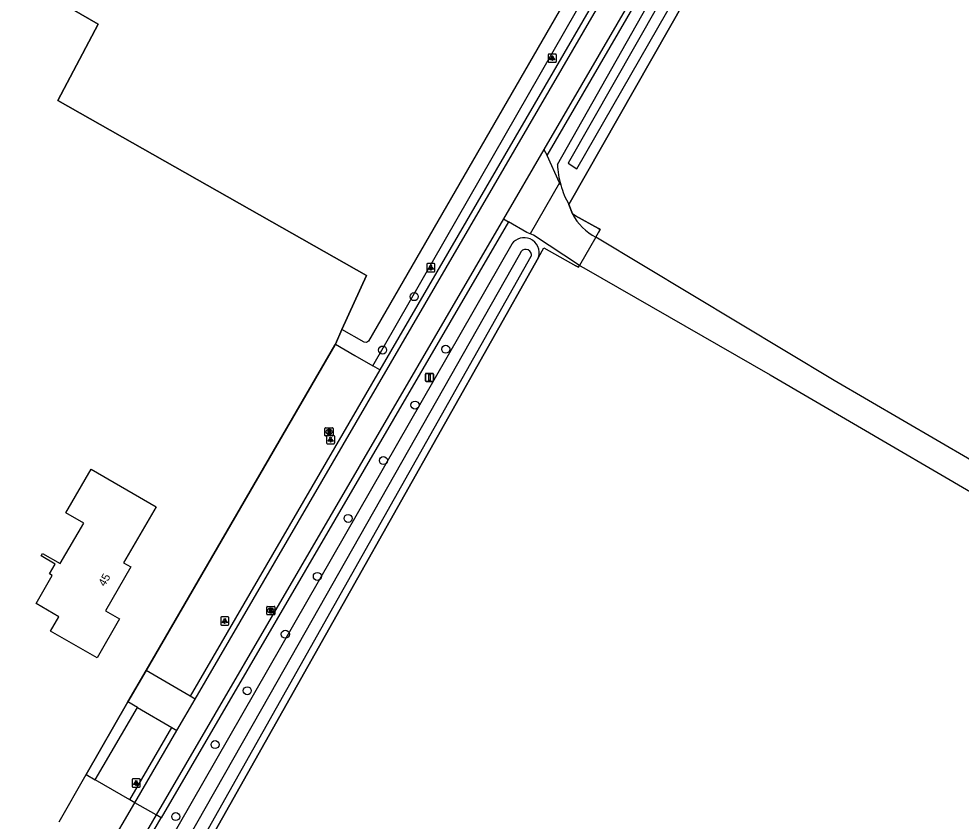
# Model space of a CAD drawing. Extents: x 156502 to 159074, y 384229 to 386094.
# Drawn here: x 157332.2 to 157446.9, y 385788.7 to 385886.4 of the extents above; entities that cross this region are included whole.
import ezdxf

# ---------------------------------------------------------------- set-up
doc = ezdxf.new("R2010")
doc.units = 0
for name, color, linetype in [('IMGEO_Boom', 7, 'Continuous'), ('IMGEO_Gemengd_bos', 7, 'Continuous'), ('IMGEO_Grasland_overig', 7, 'Continuous'), ('IMGEO_Greppel_droge_sloot', 7, 'Continuous'), ('IMGEO_Groenvoorziening', 7, 'Continuous'), ('IMGEO_Hek', 7, 'Continuous'), ('IMGEO_Lichtpunt', 7, 'Continuous'), ('IMGEO_Pand', 7, 'Continuous'), ('IMGEO_Pand_nummerreeks', 7, 'Continuous'), ('IMGEO_Rijbaan_lokaal_gesloten', 7, 'Continuous'), ('IMGEO_Rijbaan_lokaal_halfverhard', 7, 'Continuous'), ('IMGEO_Rijbaan_lokaal_onverhard', 7, 'Continuous'), ('IMGEO_Rijbaan_lokaal_open', 7, 'Continuous'), ('IMGEO_Rioolput', 7, 'Continuous'), ('IMGEO_Verkeersbordpaal', 7, 'Continuous')]:
    doc.layers.add(name, color=color, linetype=linetype)

msp = doc.modelspace()

# ---------------------------------------------------------------- linework, layer by layer
at = {"layer": 'IMGEO_Boom'}
for centre in [(157380.34, 385852.55), (157376.49, 385846.05), (157384.18, 385846.15), (157380.44, 385839.35), (157376.59, 385832.59), (157372.3, 385825.54), (157368.55, 385818.48), (157364.65, 385811.44), (157360.02, 385804.56), (157356.1, 385798), (157351.31, 385789.23)]:
    msp.add_circle(centre, 0.489, dxfattribs=at)
at = {"layer": 'IMGEO_Gemengd_bos'}
for points in [[(157371.55, 385848.55), (157374.53, 385855.11), (157336.95, 385876.45), (157341.88, 385885.73), (157297.29, 385911.48), (157291.8, 385905.79), (157257.61, 385922.62), (157240.01, 385933.44), (157265.45, 385970.38), (157218.89, 386000), (157178.39, 386025.76)], [(157395.47, 385857.33), (157396.13, 385858.5), (157400.02, 385856.3), (157400.33, 385856.13), (157400.45, 385856.36)], [(157395.47, 385857.33), (157372.59, 385816.74), (157334.96, 385750), (157287.88, 385668.68), (157271.39, 385640.19), (157191.03, 385500), (157152.55, 385432.88), (157150.67, 385429.59), (157146.17, 385421.74)]]:
    msp.add_lwpolyline(points, dxfattribs=at)
at = {"layer": 'IMGEO_Grasland_overig'}
for points in [[(157397.77, 385868.65), (157428.58, 385923.13)], [(157399.18, 385863.76), (157431.49, 385920.54)], [(157402.46, 385859.79), (157402.78, 385860.35), (157402.98, 385860.72), (157402.78, 385860.83), (157399.98, 385862.41), (157399.61, 385862.62)]]:
    msp.add_lwpolyline(points, dxfattribs=at)
msp.add_arc((157409.36, 385869.3), 11.61, 183.2027, 195.7368, dxfattribs=at)
at = {"layer": 'IMGEO_Greppel_droge_sloot'}
for points in [[(157375.29, 385844.13), (157410.37, 385905.3), (157420.59, 385922.78), (157421.74, 385925.12)], [(157419.09, 385923.89), (157374.77, 385847.13), (157374.53, 385846.95), (157374.24, 385846.99), (157371.55, 385848.55)], [(157617.36, 385817.91), (157432.79, 385923.31), (157430.69, 385923.14), (157429.39, 385922.01), (157399.07, 385868.79), (157400.14, 385868.11), (157430.83, 385921.58), (157431.57, 385921.75), (157432.56, 385921.64), (157433.69, 385921.16), (157694.94, 385770.98), (157787.76, 385718.79), (157788.5, 385720.1), (157617.36, 385817.91)], [(157393.36, 385858.05), (157393.11, 385857.61), (157362.75, 385804.11), (157325.82, 385739.17), (157293.92, 385684.22), (157277.51, 385655.56), (157259.26, 385623.71), (157238.62, 385587.75), (157224.85, 385563.79), (157203.07, 385525.9), (157174.27, 385475.36), (157161.25, 385452.05), (157151.08, 385433.93), (157146.7, 385427.27), (157144.86, 385424.97)], [(157146.46, 385424.36), (157148.98, 385428.05), (157150.58, 385430.99), (157151.89, 385433.4), (157190.31, 385500.41), (157270.67, 385640.6), (157287.16, 385669.09), (157334.24, 385750.41), (157371.86, 385817.15), (157394.6, 385857.47)], [(157370.74, 385846.77), (157371.55, 385848.55)], [(157370.74, 385846.77), (157373.11, 385845.39), (157375.29, 385844.13)]]:
    msp.add_lwpolyline(points, dxfattribs=at)
msp.add_arc((157393.91, 385857.6), 0.705, 349.121, 140.2266, dxfattribs=at)
at = {"layer": 'IMGEO_Groenvoorziening'}
for points in [[(157284.2, 385670.89), (157329.73, 385750), (157392.25, 385858.97)], [(157347.71, 385807.02), (157370.69, 385846.65), (157370.74, 385846.77)], [(157376.15, 385843.62), (157375.29, 385844.13)], [(157340.4, 385794.34), (157345.49, 385803.19)], [(157341.5, 385793.71), (157346.66, 385802.51)]]:
    msp.add_lwpolyline(points, dxfattribs=at)
for start, end in [(67.0573, 144.2272), (341.677, 66.9971)]:
    msp.add_arc((157393.73, 385857.9), 1.83, start, end, dxfattribs=at)
at = {"layer": 'IMGEO_Hek'}
for points in [[(157240.01, 385933.44), (157257.61, 385922.62), (157291.8, 385905.79), (157297.29, 385911.48), (157341.88, 385885.73), (157336.95, 385876.45), (157374.53, 385855.11), (157371.55, 385848.55)], [(157431.49, 385920.54), (157399.18, 385863.76)], [(157399.18, 385863.76), (157399.61, 385862.62)], [(157399.61, 385862.62), (157399.98, 385862.41)], [(157399.98, 385862.41), (157402.78, 385860.83)], [(157402.78, 385860.83), (157402.98, 385860.72)], [(157402.98, 385860.72), (157402.78, 385860.35)], [(157402.46, 385859.79), (157400.45, 385856.36)], [(157395.47, 385857.33), (157396.13, 385858.5)], [(157396.13, 385858.5), (157400.02, 385856.3)], [(157372.59, 385816.74), (157395.47, 385857.33)], [(157400.33, 385856.13), (157400.02, 385856.3)], [(157371.55, 385848.55), (157370.74, 385846.77)], [(157370.74, 385846.77), (157370.69, 385846.65), (157347.71, 385807.02)], [(157334.96, 385750), (157372.59, 385816.74)], [(157347.71, 385807.02), (157345.49, 385803.19)], [(157345.49, 385803.19), (157340.4, 385794.34)]]:
    msp.add_lwpolyline(points, dxfattribs=at)
at = {"layer": 'IMGEO_Lichtpunt'}
for p, q in [((157396.65, 385882), (157396.65, 385881.19)), ((157396.65, 385882), (157396.65, 385881.19)), ((157397.55, 385882.09), (157396.75, 385882.09)), ((157397.55, 385882.09), (157396.75, 385882.09)), ((157397.65, 385881.19), (157397.65, 385882)), ((157397.65, 385881.19), (157397.65, 385882)), ((157396.75, 385881.09), (157397.55, 385881.09)), ((157396.75, 385881.09), (157397.55, 385881.09)), ((157381.86, 385856.48), (157381.86, 385855.68)), ((157381.86, 385856.48), (157381.86, 385855.68)), ((157382.77, 385856.58), (157381.96, 385856.58)), ((157382.77, 385856.58), (157381.96, 385856.58)), ((157381.96, 385855.58), (157382.77, 385855.58)), ((157381.96, 385855.58), (157382.77, 385855.58)), ((157382.86, 385855.68), (157382.86, 385856.48)), ((157382.86, 385855.68), (157382.86, 385856.48)), ((157369.66, 385835.54), (157369.66, 385834.74)), ((157369.66, 385835.54), (157369.66, 385834.74)), ((157370.56, 385835.64), (157369.76, 385835.64)), ((157370.56, 385835.64), (157369.76, 385835.64)), ((157370.66, 385834.74), (157370.66, 385835.54)), ((157370.66, 385834.74), (157370.66, 385835.54)), ((157369.76, 385834.64), (157370.56, 385834.64)), ((157369.76, 385834.64), (157370.56, 385834.64)), ((157356.78, 385813.46), (157356.78, 385812.66)), ((157356.78, 385813.46), (157356.78, 385812.66)), ((157357.68, 385813.56), (157356.88, 385813.56)), ((157357.68, 385813.56), (157356.88, 385813.56)), ((157357.78, 385812.66), (157357.78, 385813.46)), ((157357.78, 385812.66), (157357.78, 385813.46)), ((157356.88, 385812.56), (157357.68, 385812.56)), ((157356.88, 385812.56), (157357.68, 385812.56)), ((157345.99, 385793.71), (157345.99, 385792.91)), ((157345.99, 385793.71), (157345.99, 385792.91)), ((157346.9, 385793.81), (157346.09, 385793.81)), ((157346.9, 385793.81), (157346.09, 385793.81)), ((157346.99, 385792.91), (157346.99, 385793.71)), ((157346.99, 385792.91), (157346.99, 385793.71)), ((157346.09, 385792.81), (157346.9, 385792.81)), ((157346.09, 385792.81), (157346.9, 385792.81))]:
    msp.add_line(p, q, dxfattribs=at)
for points in [[(157397.03, 385881.66), (157397.06, 385881.63), (157396.88, 385881.37), (157396.84, 385881.4), (157397.03, 385881.66)], [(157397.13, 385881.61), (157397.17, 385881.61), (157397.17, 385881.29), (157397.13, 385881.29), (157397.13, 385881.61)], [(157397.24, 385881.63), (157397.28, 385881.66), (157397.46, 385881.4), (157397.42, 385881.37), (157397.24, 385881.63)], [(157382.24, 385856.15), (157382.28, 385856.12), (157382.09, 385855.86), (157382.05, 385855.89), (157382.24, 385856.15)], [(157382.34, 385856.1), (157382.39, 385856.1), (157382.39, 385855.78), (157382.34, 385855.78), (157382.34, 385856.1)], [(157382.45, 385856.12), (157382.49, 385856.15), (157382.68, 385855.88), (157382.64, 385855.86), (157382.45, 385856.12)], [(157370.04, 385835.21), (157370.07, 385835.18), (157369.89, 385834.92), (157369.85, 385834.94), (157370.04, 385835.21)], [(157370.14, 385835.16), (157370.19, 385835.16), (157370.19, 385834.84), (157370.14, 385834.84), (157370.14, 385835.16)], [(157370.25, 385835.18), (157370.29, 385835.21), (157370.47, 385834.94), (157370.43, 385834.92), (157370.25, 385835.18)], [(157357.16, 385813.13), (157357.19, 385813.1), (157357.01, 385812.84), (157356.97, 385812.86), (157357.16, 385813.13)], [(157357.26, 385813.08), (157357.3, 385813.08), (157357.3, 385812.76), (157357.26, 385812.76), (157357.26, 385813.08)], [(157357.37, 385813.1), (157357.41, 385813.13), (157357.59, 385812.86), (157357.55, 385812.84), (157357.37, 385813.1)], [(157346.37, 385793.38), (157346.41, 385793.35), (157346.22, 385793.09), (157346.18, 385793.12), (157346.37, 385793.38)], [(157346.47, 385793.33), (157346.52, 385793.33), (157346.52, 385793.01), (157346.47, 385793.01), (157346.47, 385793.33)], [(157346.58, 385793.35), (157346.62, 385793.38), (157346.81, 385793.11), (157346.77, 385793.09), (157346.58, 385793.35)]]:
    msp.add_lwpolyline(points, dxfattribs=at)
for centre in [(157397.15, 385881.79), (157382.36, 385856.28), (157370.16, 385835.34), (157357.28, 385813.26), (157346.49, 385793.51)]:
    msp.add_circle(centre, 0.0994, dxfattribs=at)
for centre, start, end in [((157396.75, 385882), 90, 180), ((157396.75, 385882), 90, 180), ((157397.55, 385882), 0, 90), ((157397.55, 385882), 0, 90), ((157396.75, 385881.19), 180, 270), ((157396.75, 385881.19), 180, 270), ((157397.55, 385881.19), 270, 0), ((157397.55, 385881.19), 270, 360), ((157381.96, 385856.48), 90, 180), ((157381.96, 385856.48), 90, 180), ((157381.96, 385855.68), 180, 270), ((157381.96, 385855.68), 180, 270), ((157382.77, 385856.48), 0, 90), ((157382.77, 385856.48), 0, 90), ((157382.77, 385855.68), 270, 0), ((157382.77, 385855.68), 270, 360), ((157369.76, 385835.54), 90, 180), ((157369.76, 385835.54), 90, 180), ((157370.56, 385835.54), 0, 90), ((157370.56, 385835.54), 0, 90), ((157369.76, 385834.74), 180, 270), ((157369.76, 385834.74), 180, 270), ((157370.56, 385834.74), 270, 0), ((157370.56, 385834.74), 270, 360), ((157356.88, 385813.46), 90, 180), ((157356.88, 385813.46), 90, 180), ((157357.68, 385813.46), 0, 90), ((157357.68, 385813.46), 0, 90), ((157356.88, 385812.66), 180, 270), ((157356.88, 385812.66), 180, 270), ((157357.68, 385812.66), 270, 0), ((157357.68, 385812.66), 270, 360), ((157346.09, 385793.71), 90, 180), ((157346.09, 385793.71), 90, 180), ((157346.9, 385793.71), 0, 90), ((157346.9, 385793.71), 0, 90), ((157346.09, 385792.91), 180, 270), ((157346.09, 385792.91), 180, 270), ((157346.9, 385792.91), 270, 0), ((157346.9, 385792.91), 270, 360)]:
    msp.add_arc(centre, 0.0946, start, end, dxfattribs=at)
at = {"layer": 'IMGEO_Pand'}
msp.add_lwpolyline([(157341.02, 385831.54), (157348.92, 385826.96), (157344.96, 385820.12), (157345.83, 385819.63), (157342.75, 385814.3), (157344.48, 385813.31), (157341.74, 385808.56), (157336.08, 385811.83), (157337.08, 385813.57), (157334.3, 385815.17), (157336.28, 385818.6), (157335.94, 385818.8), (157336.63, 385819.98), (157334.91, 385820.98), (157335.08, 385821.29), (157337.24, 385820.04), (157340.1, 385824.97), (157337.94, 385826.22), (157341.02, 385831.54)], dxfattribs=at)
at = {"layer": 'IMGEO_Rijbaan_lokaal_gesloten'}
for points in [[(157353.67, 385803.53), (157424.73, 385925.73), (157424.2, 385926.06)], [(157427.79, 385923.96), (157427.36, 385924.19), (157396.12, 385870.48)], [(157396.12, 385870.48), (157391.21, 385862.03)], [(157398.05, 385866.43), (157394.47, 385860.19)], [(157398.19, 385866.15), (157398.05, 385866.43)], [(157399.61, 385862.62), (157399.18, 385863.76)], [(157391.21, 385862.03), (157348.91, 385789.44)], [(157400.45, 385856.36), (157394.87, 385860.03), (157394.47, 385860.19)], [(157402.46, 385859.79), (157400.45, 385856.36)], [(157351.44, 385799.71), (157353.67, 385803.53)], [(157346.33, 385790.92), (157351.44, 385799.71)], [(157348.91, 385789.44), (157346.33, 385790.92)]]:
    msp.add_lwpolyline(points, dxfattribs=at)
for centre, radius, start, end in [((157407.96, 385868.82), 10.13, 195.2681, 209.9682), ((157405.51, 385865.72), 6.67, 207.6827, 242.7409)]:
    msp.add_arc(centre, radius, start, end, dxfattribs=at)
at = {"layer": 'IMGEO_Rijbaan_lokaal_halfverhard'}
for points in [[(157423.29, 385924.72), (157376.15, 385843.62)], [(157396.52, 385869.73), (157427.96, 385923.81)], [(157391.83, 385861.67), (157349.52, 385789.09)], [(157376.15, 385843.62), (157353.05, 385803.89)], [(157345.49, 385803.19), (157347.71, 385807.02)], [(157353.05, 385803.89), (157347.71, 385807.02)], [(157353.67, 385803.53), (157353.05, 385803.89)], [(157346.66, 385802.51), (157345.49, 385803.19)], [(157346.66, 385802.51), (157350.82, 385800.07)], [(157345.7, 385791.29), (157350.82, 385800.07)], [(157350.82, 385800.07), (157351.44, 385799.71)], [(157281.97, 385672.23), (157287.9, 385682.57), (157297.81, 385699.74), (157305.61, 385713.27), (157310.6, 385721.93), (157349.52, 385789.09)], [(157349.52, 385789.09), (157348.91, 385789.44)]]:
    msp.add_lwpolyline(points, dxfattribs=at)
at = {"layer": 'IMGEO_Rijbaan_lokaal_onverhard'}
for points in [[(157651.55, 385713.58), (157640.83, 385721.01), (157618.9, 385733.88), (157569.6, 385763.21), (157489.99, 385808.25), (157431.47, 385842.35), (157402.46, 385859.79)], [(157400.45, 385856.36), (157401.01, 385856.04), (157423.67, 385843.01), (157458.7, 385822.57), (157479.2, 385810.14)]]:
    msp.add_lwpolyline(points, dxfattribs=at)
at = {"layer": 'IMGEO_Rijbaan_lokaal_open'}
for points in [[(157396.12, 385870.48), (157396.52, 385869.73)], [(157398.05, 385866.43), (157396.52, 385869.73)], [(157391.21, 385862.03), (157391.83, 385861.67)], [(157394.47, 385860.19), (157394.07, 385860.35), (157391.83, 385861.67)], [(157337.11, 385788.6), (157340.4, 385794.34)], [(157340.4, 385794.34), (157341.5, 385793.71)], [(157345.7, 385791.29), (157341.5, 385793.71)], [(157346.33, 385790.92), (157345.7, 385791.29)], [(157342.98, 385785.16), (157346.33, 385790.92)], [(157348.91, 385789.44), (157309.98, 385722.29), (157304.98, 385713.63), (157297.19, 385700.1), (157287.28, 385682.93), (157276.98, 385664.99), (157272.99, 385658.15), (157259.7, 385634.92)]]:
    msp.add_lwpolyline(points, dxfattribs=at)
at = {"layer": 'IMGEO_Rioolput'}
for p, q in [((157369.48, 385835.66), (157369.48, 385836.51)), ((157369.55, 385836.59), (157370.4, 385836.59)), ((157369.96, 385836.37), (157369.99, 385836.37)), ((157370.48, 385836.51), (157370.48, 385835.66)), ((157370.4, 385835.59), (157369.55, 385835.59)), ((157369.99, 385835.81), (157369.96, 385835.81)), ((157362.38, 385813.9), (157362.38, 385814.75)), ((157362.45, 385814.83), (157363.31, 385814.83)), ((157362.87, 385814.6), (157362.89, 385814.6)), ((157363.38, 385814.75), (157363.38, 385813.9)), ((157363.31, 385813.82), (157362.45, 385813.82)), ((157362.89, 385814.05), (157362.87, 385814.05))]:
    msp.add_line(p, q, dxfattribs=at)
for points in [[(157369.48, 385835.66), (157369.48, 385836.51)], [(157369.55, 385836.59), (157370.4, 385836.59)], [(157370.07, 385836.28), (157369.81, 385836.29), (157369.81, 385835.89)], [(157369.81, 385835.89), (157369.94, 385835.89), (157369.94, 385836.05), (157369.95, 385836.05)], [(157369.99, 385836.21), (157369.94, 385836.21), (157369.94, 385836.12)], [(157369.94, 385836.12), (157369.99, 385836.12)], [(157369.99, 385836.02), (157370.07, 385835.89), (157370.21, 385835.89), (157370.14, 385836.01)], [(157370.48, 385836.51), (157370.48, 385835.66)], [(157370.4, 385835.59), (157369.55, 385835.59)], [(157362.38, 385813.9), (157362.38, 385814.75)], [(157362.45, 385814.83), (157363.31, 385814.83)], [(157362.97, 385814.52), (157362.72, 385814.52), (157362.72, 385814.12)], [(157362.72, 385814.12), (157362.84, 385814.12), (157362.84, 385814.29), (157362.85, 385814.29)], [(157362.9, 385814.44), (157362.84, 385814.44), (157362.84, 385814.36)], [(157362.84, 385814.36), (157362.89, 385814.36)], [(157362.9, 385814.26), (157362.97, 385814.12), (157363.11, 385814.12), (157363.04, 385814.25)], [(157363.38, 385814.75), (157363.38, 385813.9)], [(157363.31, 385813.82), (157362.45, 385813.82)]]:
    msp.add_lwpolyline(points, dxfattribs=at)
for centre, radius, start, end in [((157369.55, 385836.51), 0.0765, 91.552, 178.448), ((157369.55, 385836.51), 0.0765, 91.552, 178.448), ((157369.95, 385836), 0.0533, 26.0293, 88.6989), ((157370, 385836.11), 0.0964, 77.0061, 93.1865), ((157369.97, 385836.31), 0.19, 274.7715, 282.9687), ((157370.01, 385836.17), 0.0378, 276.6634, 79.6772), ((157370.06, 385836.17), 0.109, 350.3612, 89.416), ((157370.06, 385836.17), 0.112, 277.5842, 350.9817), ((157370.05, 385835.96), 0.108, 29.5134, 73.7905), ((157370.4, 385836.51), 0.0765, 1.552, 88.448), ((157370.4, 385836.51), 0.0765, 1.552, 88.448), ((157369.55, 385835.66), 0.0765, 181.552, 268.448), ((157369.55, 385835.66), 0.0765, 181.552, 268.448), ((157370.4, 385835.66), 0.0765, 271.552, 358.448), ((157370.4, 385835.66), 0.0765, 271.552, 358.448), ((157362.46, 385814.75), 0.0765, 91.552, 178.448), ((157362.46, 385814.75), 0.0765, 91.552, 178.448), ((157362.85, 385814.23), 0.0533, 26.0293, 88.6989), ((157362.88, 385814.55), 0.19, 274.7715, 282.9687), ((157362.9, 385814.35), 0.0964, 77.0061, 93.1865), ((157362.92, 385814.4), 0.0378, 276.6634, 79.6772), ((157362.97, 385814.41), 0.109, 350.3612, 89.416), ((157362.97, 385814.41), 0.112, 277.5842, 350.9817), ((157362.95, 385814.2), 0.108, 29.5134, 73.7905), ((157363.3, 385814.75), 0.0765, 1.552, 88.448), ((157363.3, 385814.75), 0.0765, 1.552, 88.448), ((157362.46, 385813.9), 0.0765, 181.552, 268.448), ((157362.46, 385813.9), 0.0765, 181.552, 268.448), ((157363.3, 385813.9), 0.0765, 271.552, 358.448), ((157363.3, 385813.9), 0.0765, 271.552, 358.448)]:
    msp.add_arc(centre, radius, start, end, dxfattribs=at)
for centre, major_axis, ratio, start_param, end_param in [((157369.96, 385836.09), (-0.387, 0.002), 0.722429, 4.712389, 7.853982), ((157369.99, 385836.09), (-0.39, 0.002), 0.717154, 1.570796, 4.712389), ((157362.87, 385814.32), (-0.387, 0.002), 0.722429, 4.712389, 7.853982), ((157362.89, 385814.32), (-0.39, 0.002), 0.717154, 1.570796, 4.712389)]:
    msp.add_ellipse(centre, major_axis=major_axis, ratio=ratio, start_param=start_param, end_param=end_param, dxfattribs=at)
at = {"layer": 'IMGEO_Verkeersbordpaal'}
for p, q in [((157381.7, 385842.31), (157381.7, 385843.11)), ((157381.7, 385843.11), (157381.7, 385842.31)), ((157381.8, 385843.21), (157382.59, 385843.21)), ((157382.59, 385843.21), (157381.8, 385843.21)), ((157382.69, 385843.11), (157382.69, 385842.31)), ((157382.69, 385842.31), (157382.69, 385843.11)), ((157382.59, 385842.21), (157381.8, 385842.21)), ((157381.8, 385842.21), (157382.59, 385842.21))]:
    msp.add_line(p, q, dxfattribs=at)
msp.add_lwpolyline([(157382.12, 385843.08), (157382.27, 385843.08), (157382.27, 385842.33), (157382.12, 385842.33), (157382.12, 385843.08)], dxfattribs=at)
for centre, start, end in [((157381.8, 385843.11), 90, 180), ((157381.8, 385843.11), 90, 180), ((157382.59, 385843.11), 0, 90), ((157382.59, 385843.11), 360, 90), ((157381.8, 385842.31), 180, 270), ((157381.8, 385842.31), 180, 270), ((157382.59, 385842.31), 270, 0), ((157382.59, 385842.31), 270, 0)]:
    msp.add_arc(centre, 0.1, start, end, dxfattribs=at)

# ---------------------------------------------------------------- texts
at = {"layer": 'IMGEO_Pand_nummerreeks'}
msp.add_text('45', height=1, rotation=60.0059, dxfattribs=at).set_placement((157342.67, 385817.17))

doc.saveas('drawing.dxf')
